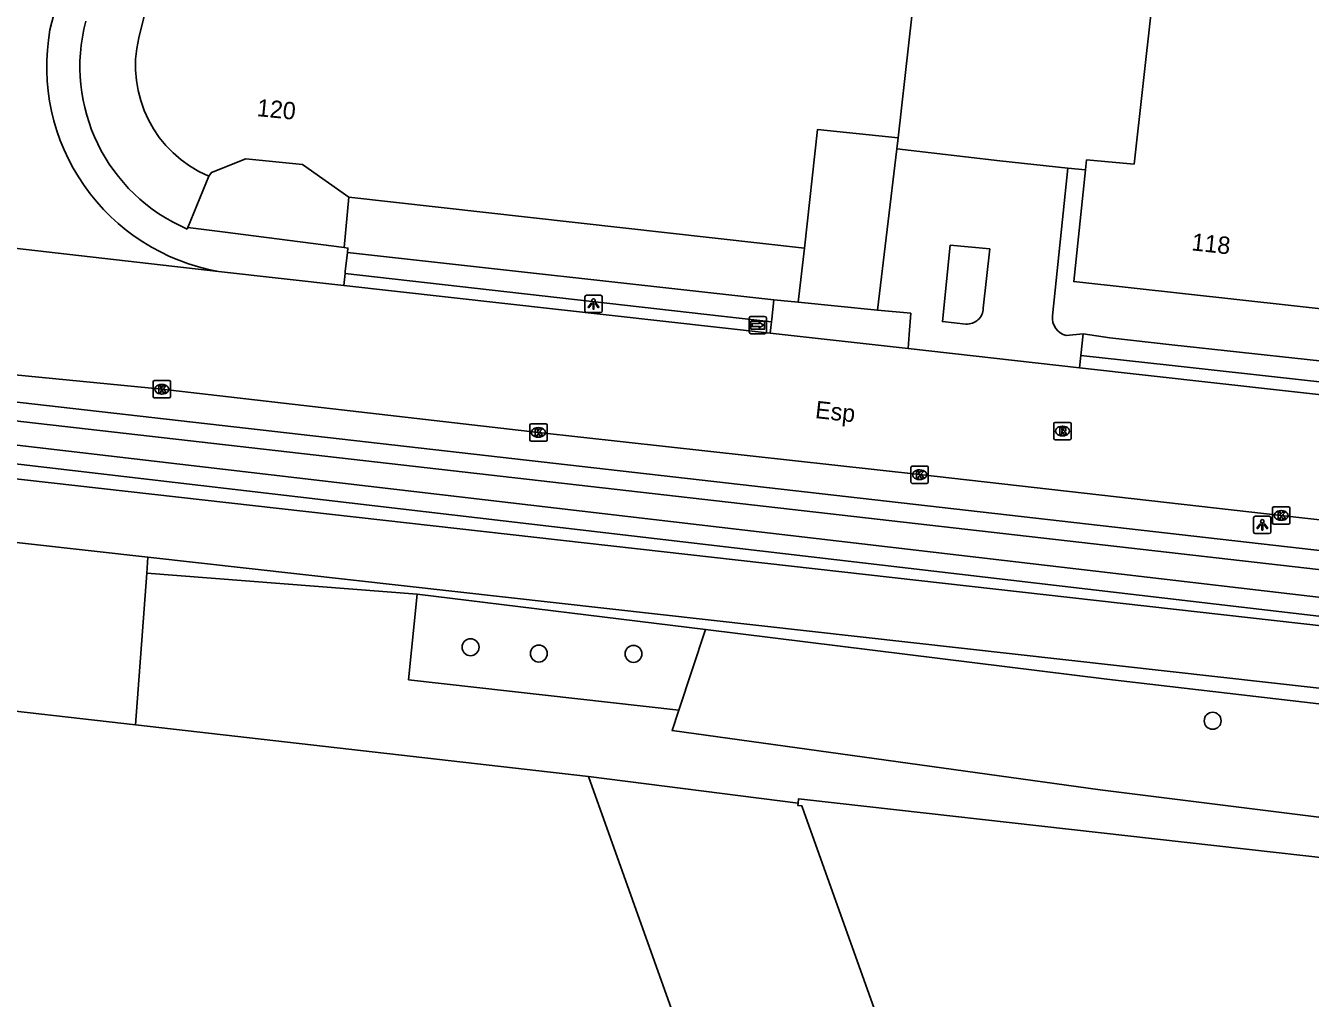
# Model space of a CAD drawing. Extents: x 161389 to 162585, y 388479 to 389761.
# Drawn here: x 162205 to 162279.1, y 388650.1 to 388706.2 of the extents above; entities that cross this region are included whole.
import ezdxf

# ---------------------------------------------------------------- set-up
doc = ezdxf.new("R2010")
doc.units = 0
for name, color, linetype in [('IMGEO_Berm_groen', 7, 'Continuous'), ('IMGEO_Boom', 7, 'Continuous'), ('IMGEO_Erf', 7, 'Continuous'), ('IMGEO_Fietspad_gesloten', 7, 'Continuous'), ('IMGEO_Groenvoorziening', 7, 'Continuous'), ('IMGEO_Hek', 7, 'Continuous'), ('IMGEO_Kolk', 7, 'Continuous'), ('IMGEO_Lichtpunt', 7, 'Continuous'), ('IMGEO_Openbare_ruimte_label', 7, 'Continuous'), ('IMGEO_Pand', 7, 'Continuous'), ('IMGEO_Pand_nummerreeks', 7, 'Continuous'), ('IMGEO_Rijbaan_lokaal_gesloten', 7, 'Continuous'), ('IMGEO_Rijbaan_lokaal_open', 7, 'Continuous'), ('IMGEO_Rioolput', 7, 'Continuous'), ('IMGEO_Voetpad_open', 7, 'Continuous'), ('IMGEO_Waterloop', 7, 'Continuous'), ('IMGEO_Wegwijzer', 7, 'Continuous')]:
    doc.layers.add(name, color=color, linetype=linetype)

msp = doc.modelspace()

# ---------------------------------------------------------------- linework, layer by layer
at = {"layer": 'IMGEO_Berm_groen'}
for points in [[(162195.511, 388685.399), (162199.258, 388685.044), (162309.372, 388672.493), (162313.677, 388672.019)], [(162314.929, 388670.455), (162314.838, 388669.228), (162314.739, 388669.003), (162314.316, 388668.451), (162313.561, 388668.026), (162313.044, 388667.945), (162308.893, 388668.677), (162198.797, 388681.534), (162194.824, 388681.685), (162194.516, 388681.817), (162194.124, 388682.146), (162193.837, 388682.714), (162193.797, 388682.968), (162193.974, 388684.393)], [(162212.05, 388675.493), (162211.982, 388674.58)], [(162227.587, 388673.375), (162211.982, 388674.58)], [(162227.587, 388673.375), (162244.211, 388671.327)], [(162244.211, 388671.327), (162267.366, 388668.474), (162328.021, 388661.404)]]:
    msp.add_lwpolyline(points, dxfattribs=at)
at = {"layer": 'IMGEO_Boom'}
for centre in [(162230.659, 388670.305), (162234.598, 388669.941), (162240.061, 388669.921), (162273.473, 388666.067)]:
    msp.add_circle(centre, 0.489, dxfattribs=at)
at = {"layer": 'IMGEO_Erf'}
msp.add_lwpolyline([(162265.115, 388697.944), (162266.146, 388697.835)], dxfattribs=at)
at = {"layer": 'IMGEO_Fietspad_gesloten'}
for points in [[(162190.209, 388681.612), (162327.081, 388666.21)], [(162212.05, 388675.493), (162188.441, 388678.131)], [(162328.163, 388662.672), (162327.44, 388662.75), (162327.383, 388662.532), (162314.863, 388664.007), (162212.05, 388675.493)]]:
    msp.add_lwpolyline(points, dxfattribs=at)
at = {"layer": 'IMGEO_Groenvoorziening'}
for points in [[(162211.982, 388674.58), (162211.331, 388665.832)], [(162242.681, 388666.67), (162227.085, 388668.43), (162227.587, 388673.375)], [(162242.681, 388666.67), (162244.211, 388671.327)], [(162327.291, 388654.887), (162309.928, 388656.723), (162266.988, 388662.085), (162242.291, 388665.501), (162242.681, 388666.67)], [(162237.455, 388662.849), (162249.555, 388661.32)]]:
    msp.add_lwpolyline(points, dxfattribs=at)
at = {"layer": 'IMGEO_Hek'}
for points in [[(162261.196, 388698.356), (162255.245, 388699.047)], [(162265.115, 388697.944), (162261.196, 388698.356)], [(162266.146, 388697.835), (162265.115, 388697.944)]]:
    msp.add_lwpolyline(points, dxfattribs=at)
at = {"layer": 'IMGEO_Kolk'}
for p, q in [((162212.35, 388684.76), (162212.35, 388685.612)), ((162212.425, 388685.686), (162213.277, 388685.686)), ((162212.838, 388685.466), (162212.863, 388685.466)), ((162213.351, 388685.612), (162213.351, 388684.76)), ((162213.277, 388684.686), (162212.425, 388684.686)), ((162212.861, 388684.906), (162212.836, 388684.906)), ((162234.072, 388682.27), (162234.072, 388683.122)), ((162234.147, 388683.196), (162234.999, 388683.196)), ((162234.56, 388682.976), (162234.585, 388682.976)), ((162235.073, 388683.122), (162235.073, 388682.27)), ((162234.999, 388682.196), (162234.147, 388682.196)), ((162234.583, 388682.416), (162234.558, 388682.416)), ((162256.068, 388679.833), (162256.068, 388680.685)), ((162256.143, 388680.759), (162256.995, 388680.759)), ((162256.556, 388680.539), (162256.581, 388680.539)), ((162257.069, 388680.685), (162257.069, 388679.833)), ((162256.995, 388679.759), (162256.143, 388679.759)), ((162256.579, 388679.979), (162256.554, 388679.979)), ((162276.927, 388677.48), (162276.927, 388678.332)), ((162277.002, 388678.406), (162277.854, 388678.406)), ((162277.415, 388678.186), (162277.44, 388678.186)), ((162277.928, 388678.332), (162277.928, 388677.48)), ((162277.854, 388677.406), (162277.002, 388677.406)), ((162277.438, 388677.626), (162277.413, 388677.626))]:
    msp.add_line(p, q, dxfattribs=at)
for points in [[(162212.35, 388684.76), (162212.35, 388685.612)], [(162212.425, 388685.686), (162213.277, 388685.686)], [(162213.351, 388685.612), (162213.351, 388684.76)], [(162213.277, 388684.686), (162212.425, 388684.686)], [(162212.671, 388685.386), (162212.794, 388685.386), (162212.794, 388685.235), (162212.924, 388685.386), (162213.088, 388685.386), (162212.942, 388685.235), (162213.095, 388684.986), (162212.943, 388684.986), (162212.858, 388685.15), (162212.794, 388685.083), (162212.794, 388684.986), (162212.671, 388684.986), (162212.671, 388685.386)], [(162234.072, 388682.27), (162234.072, 388683.122)], [(162234.147, 388683.196), (162234.999, 388683.196)], [(162234.393, 388682.896), (162234.516, 388682.896), (162234.516, 388682.745), (162234.646, 388682.896), (162234.81, 388682.896), (162234.664, 388682.745), (162234.817, 388682.496), (162234.665, 388682.496), (162234.58, 388682.66), (162234.516, 388682.593), (162234.516, 388682.496), (162234.393, 388682.496), (162234.393, 388682.896)], [(162235.073, 388683.122), (162235.073, 388682.27)], [(162234.999, 388682.196), (162234.147, 388682.196)], [(162256.068, 388679.833), (162256.068, 388680.685)], [(162256.143, 388680.759), (162256.995, 388680.759)], [(162256.389, 388680.459), (162256.512, 388680.459), (162256.512, 388680.308), (162256.642, 388680.459), (162256.806, 388680.459), (162256.66, 388680.308), (162256.813, 388680.059), (162256.661, 388680.059), (162256.576, 388680.223), (162256.512, 388680.156), (162256.512, 388680.059), (162256.389, 388680.059), (162256.389, 388680.459)], [(162257.069, 388680.685), (162257.069, 388679.833)], [(162256.995, 388679.759), (162256.143, 388679.759)], [(162276.927, 388677.48), (162276.927, 388678.332)], [(162277.002, 388678.406), (162277.854, 388678.406)], [(162277.248, 388678.106), (162277.371, 388678.106), (162277.371, 388677.955), (162277.501, 388678.106), (162277.665, 388678.106), (162277.519, 388677.955), (162277.672, 388677.706), (162277.52, 388677.706), (162277.435, 388677.87), (162277.371, 388677.803), (162277.371, 388677.706), (162277.248, 388677.706), (162277.248, 388678.106)], [(162277.928, 388678.332), (162277.928, 388677.48)], [(162277.854, 388677.406), (162277.002, 388677.406)]]:
    msp.add_lwpolyline(points, dxfattribs=at)
for centre, start, end in [((162212.427, 388685.61), 91.55205, 178.44795), ((162212.427, 388685.61), 91.55205, 178.44795), ((162213.275, 388685.61), 1.55205, 88.44795), ((162213.275, 388685.61), 1.55205, 88.44795), ((162212.427, 388684.762), 181.55205, 268.44795), ((162212.427, 388684.762), 181.55205, 268.44795), ((162213.275, 388684.762), 271.55205, 358.44795), ((162213.275, 388684.762), 271.55205, 358.44795), ((162234.149, 388683.12), 91.55205, 178.44795), ((162234.149, 388683.12), 91.55205, 178.44795), ((162234.997, 388683.12), 1.55205, 88.44795), ((162234.997, 388683.12), 1.55205, 88.44795), ((162234.149, 388682.272), 181.55205, 268.44795), ((162234.149, 388682.272), 181.55205, 268.44795), ((162234.997, 388682.272), 271.55205, 358.44795), ((162234.997, 388682.272), 271.55205, 358.44795), ((162256.145, 388680.683), 91.55205, 178.44795), ((162256.145, 388680.683), 91.55205, 178.44795), ((162256.993, 388680.683), 1.55205, 88.44795), ((162256.993, 388680.683), 1.55205, 88.44795), ((162256.145, 388679.835), 181.55205, 268.44795), ((162256.145, 388679.835), 181.55205, 268.44795), ((162256.993, 388679.835), 271.55205, 358.44795), ((162256.993, 388679.835), 271.55205, 358.44795), ((162277.004, 388678.33), 91.55205, 178.44795), ((162277.004, 388678.33), 91.55205, 178.44795), ((162277.852, 388678.33), 1.55205, 88.44795), ((162277.852, 388678.33), 1.55205, 88.44795), ((162277.004, 388677.482), 181.55205, 268.44795), ((162277.004, 388677.482), 181.55205, 268.44795), ((162277.852, 388677.482), 271.55205, 358.44795), ((162277.852, 388677.482), 271.55205, 358.44795)]:
    msp.add_arc(centre, 0.0765, start, end, dxfattribs=at)
for centre, major_axis, ratio, start_param, end_param in [((162212.837, 388685.186), (-0.387, 0.002), 0.722429, 4.712389, 7.853982), ((162212.862, 388685.186), (-0.39, 0.002), 0.717154, 1.570796, 4.712389), ((162234.559, 388682.696), (-0.387, 0.002), 0.722429, 4.712389, 7.853982), ((162234.584, 388682.696), (-0.39, 0.002), 0.717154, 1.570796, 4.712389), ((162256.555, 388680.259), (-0.387, 0.002), 0.722429, 4.712389, 7.853982), ((162256.58, 388680.259), (-0.39, 0.002), 0.717154, 1.570796, 4.712389), ((162277.414, 388677.906), (-0.387, 0.002), 0.722429, 4.712389, 7.853982), ((162277.439, 388677.906), (-0.39, 0.002), 0.717154, 1.570796, 4.712389)]:
    msp.add_ellipse(centre, major_axis=major_axis, ratio=ratio, start_param=start_param, end_param=end_param, dxfattribs=at)
at = {"layer": 'IMGEO_Lichtpunt'}
for p, q in [((162237.256, 388690.513), (162237.256, 388689.706)), ((162237.256, 388690.513), (162237.256, 388689.706)), ((162238.158, 388690.608), (162237.35, 388690.608)), ((162238.158, 388690.608), (162237.35, 388690.608)), ((162238.252, 388689.706), (162238.252, 388690.513)), ((162238.252, 388689.706), (162238.252, 388690.513)), ((162237.35, 388689.612), (162238.158, 388689.612)), ((162237.35, 388689.612), (162238.158, 388689.612)), ((162275.838, 388677.768), (162275.838, 388676.961)), ((162275.838, 388677.768), (162275.838, 388676.961)), ((162276.74, 388677.863), (162275.932, 388677.863)), ((162276.74, 388677.863), (162275.932, 388677.863)), ((162276.834, 388676.961), (162276.834, 388677.768)), ((162276.834, 388676.961), (162276.834, 388677.768)), ((162275.932, 388676.867), (162276.74, 388676.867)), ((162275.932, 388676.867), (162276.74, 388676.867))]:
    msp.add_line(p, q, dxfattribs=at)
for points in [[(162237.63, 388690.177), (162237.669, 388690.149), (162237.481, 388689.887), (162237.443, 388689.914), (162237.63, 388690.177)], [(162237.732, 388690.129), (162237.779, 388690.129), (162237.779, 388689.807), (162237.732, 388689.807), (162237.732, 388690.129)], [(162237.842, 388690.149), (162237.88, 388690.176), (162238.067, 388689.914), (162238.028, 388689.886), (162237.842, 388690.149)], [(162276.212, 388677.432), (162276.251, 388677.404), (162276.063, 388677.142), (162276.025, 388677.169), (162276.212, 388677.432)], [(162276.314, 388677.384), (162276.361, 388677.384), (162276.361, 388677.062), (162276.314, 388677.062), (162276.314, 388677.384)], [(162276.424, 388677.404), (162276.462, 388677.431), (162276.649, 388677.169), (162276.61, 388677.141), (162276.424, 388677.404)]]:
    msp.add_lwpolyline(points, dxfattribs=at)
for centre in [(162237.755, 388690.311), (162276.337, 388677.566)]:
    msp.add_circle(centre, 0.0994, dxfattribs=at)
for centre, start, end in [((162237.35, 388690.513), 90, 180), ((162237.35, 388690.513), 90, 180), ((162238.158, 388690.513), 0, 90), ((162238.158, 388690.513), 0, 90), ((162237.35, 388689.706), 180, 270), ((162237.35, 388689.706), 180, 270), ((162238.158, 388689.706), 270, 0), ((162238.158, 388689.706), 270, 360), ((162275.932, 388677.768), 90, 180), ((162275.932, 388677.768), 90, 180), ((162276.74, 388677.768), 0, 90), ((162276.74, 388677.768), 0, 90), ((162275.932, 388676.961), 180, 270), ((162275.932, 388676.961), 180, 270), ((162276.74, 388676.961), 270, 0), ((162276.74, 388676.961), 270, 360)]:
    msp.add_arc(centre, 0.0946, start, end, dxfattribs=at)
at = {"layer": 'IMGEO_Pand'}
for points in [[(162211.515, 388705.449), (162220.313, 388740.719), (162227.254, 388738.96)], [(162227.254, 388738.96), (162227.068, 388738.207), (162226.351, 388735.221), (162227.54, 388735.088), (162232.571, 388734.536), (162232.77, 388734.513), (162237.406, 388733.976), (162237.604, 388733.953), (162249.955, 388732.564), (162254.514, 388732.048), (162258.439, 388731.604), (162258.899, 388731.55), (162255.335, 388699.679)], [(162266.146, 388697.835), (162266.198, 388698.415), (162268.938, 388698.17), (162272.942, 388734.017), (162287.984, 388732.337), (162288.104, 388732.324), (162284.142, 388696.552)], [(162249.919, 388693.319), (162250.682, 388700.177), (162255.335, 388699.679)], [(162215.552, 388697.486), (162215.711, 388697.693), (162217.697, 388698.472), (162220.967, 388698.149), (162223.633, 388696.259)], [(162266.146, 388697.835), (162265.455, 388691.401), (162281.314, 388689.643), (162282.073, 388696.501), (162284.111, 388696.275)], [(162223.633, 388696.259), (162249.919, 388693.319)], [(162201.171, 388666.993), (162202.802, 388662.297), (162182.158, 388654.923), (162182.252, 388654.637), (162182.743, 388654.798), (162185.543, 388646.914), (162180.831, 388645.223), (162180.558, 388645.977), (162180.164, 388645.887), (162182.655, 388638.891), (162184.222, 388634.491), (162188.677, 388621.975), (162192.555, 388611.083), (162248.797, 388631.105), (162237.455, 388662.849)], [(162211.331, 388665.832), (162201.171, 388666.993)], [(162211.331, 388665.832), (162237.455, 388662.849)], [(162249.555, 388661.32), (162249.539, 388661.179), (162249.773, 388661.153), (162249.791, 388661.103), (162278.169, 388581.632), (162278.061, 388581.594), (162278.245, 388581.061)], [(162323.903, 388652.051), (162324.031, 388653.194), (162250.099, 388661.511), (162249.582, 388661.569), (162249.555, 388661.32)]]:
    msp.add_lwpolyline(points, dxfattribs=at)
msp.add_arc((162218.235, 388703.851), 6.908, 166.62507, 247.14219, dxfattribs=at)
at = {"layer": 'IMGEO_Rijbaan_lokaal_gesloten'}
for points in [[(162206.396, 388705.918), (162206.618, 388706.811)], [(162216.117, 388691.984), (162185.651, 388695.455)], [(162223.34, 388691.176), (162216.117, 388691.984)], [(162247.951, 388688.424), (162223.34, 388691.176)], [(162255.908, 388687.535), (162247.951, 388688.424)], [(162190.731, 388687.591), (162191.691, 388687.487), (162192.948, 388687.248), (162200.409, 388686.41), (162212.852, 388685.186), (162234.573, 388682.697), (162256.569, 388680.26), (162277.429, 388677.907), (162297.925, 388675.602), (162319.739, 388673.126), (162319.871, 388673.113), (162320.835, 388672.971)], [(162265.796, 388686.429), (162255.908, 388687.535)], [(162285.607, 388684.214), (162265.796, 388686.429)]]:
    msp.add_lwpolyline(points, dxfattribs=at)
msp.add_arc((162218.198, 388703.794), 11.992, 169.79791, 260.00489, dxfattribs=at)
at = {"layer": 'IMGEO_Rijbaan_lokaal_open'}
for points in [[(162255.335, 388699.679), (162255.245, 388699.047)], [(162255.245, 388699.047), (162254.13, 388689.743)], [(162255.245, 388699.047), (162261.196, 388698.356), (162265.115, 388697.944)], [(162265.115, 388697.944), (162264.238, 388689.414)], [(162249.919, 388693.319), (162249.57, 388690.204)], [(162260.627, 388693.292), (162258.332, 388693.496), (162257.881, 388689.092), (162259.237, 388688.948)], [(162260.241, 388689.861), (162260.627, 388693.292)], [(162254.13, 388689.743), (162249.57, 388690.204)], [(162254.13, 388689.743), (162256.055, 388689.574), (162255.966, 388688.342), (162255.908, 388687.535)], [(162265.031, 388688.292), (162265.999, 388688.392)], [(162265.86, 388687.132), (162265.999, 388688.392)], [(162265.86, 388687.132), (162265.796, 388686.429)]]:
    msp.add_lwpolyline(points, dxfattribs=at)
for centre, radius, start, end in [((162259.305, 388689.881), 0.936, 265.81307, 358.75135), ((162265.253, 388689.29), 1.023, 173.04804, 257.45528)]:
    msp.add_arc(centre, radius, start, end, dxfattribs=at)
at = {"layer": 'IMGEO_Rioolput'}
for p, q in [((162264.311, 388682.35), (162264.311, 388683.202)), ((162264.386, 388683.276), (162265.238, 388683.276)), ((162265.312, 388683.202), (162265.312, 388682.35)), ((162264.822, 388682.496), (162264.797, 388682.496)), ((162264.799, 388683.056), (162264.824, 388683.056)), ((162265.238, 388682.276), (162264.386, 388682.276))]:
    msp.add_line(p, q, dxfattribs=at)
for points in [[(162264.311, 388682.35), (162264.311, 388683.202)], [(162264.386, 388683.276), (162265.238, 388683.276)], [(162265.312, 388683.202), (162265.312, 388682.35)], [(162264.9, 388682.974), (162264.648, 388682.976), (162264.648, 388682.576)], [(162264.648, 388682.576), (162264.772, 388682.576), (162264.772, 388682.738), (162264.783, 388682.738)], [(162264.826, 388682.895), (162264.772, 388682.895), (162264.772, 388682.814)], [(162264.772, 388682.814), (162264.824, 388682.814)], [(162264.83, 388682.709), (162264.901, 388682.576), (162265.041, 388682.576), (162264.976, 388682.702)], [(162265.238, 388682.276), (162264.386, 388682.276)]]:
    msp.add_lwpolyline(points, dxfattribs=at)
for centre, radius, start, end in [((162264.388, 388683.2), 0.0765, 91.55205, 178.44795), ((162264.388, 388683.2), 0.0765, 91.55205, 178.44795), ((162265.236, 388683.2), 0.0765, 1.55205, 88.44795), ((162265.236, 388683.2), 0.0765, 1.55205, 88.44795), ((162264.782, 388682.685), 0.0533, 26.02933, 88.69889), ((162264.808, 388683.003), 0.19, 274.7715, 282.96867), ((162264.832, 388682.799), 0.0964, 77.00612, 93.18647), ((162264.846, 388682.856), 0.0378, 276.66336, 79.67722), ((162264.899, 388682.864), 0.109, 350.36119, 89.41601), ((162264.897, 388682.864), 0.112, 277.58423, 350.98172), ((162264.881, 388682.649), 0.108, 29.51342, 73.79051), ((162264.388, 388682.352), 0.0765, 181.55205, 268.44795), ((162264.388, 388682.352), 0.0765, 181.55205, 268.44795), ((162265.236, 388682.352), 0.0765, 271.55205, 358.44795), ((162265.236, 388682.352), 0.0765, 271.55205, 358.44795)]:
    msp.add_arc(centre, radius, start, end, dxfattribs=at)
for centre, major_axis, ratio, start_param, end_param in [((162264.798, 388682.776), (-0.387, 0.002), 0.722429, 4.712389, 7.853982), ((162264.823, 388682.776), (-0.39, 0.002), 0.717154, 1.570796, 4.712389)]:
    msp.add_ellipse(centre, major_axis=major_axis, ratio=ratio, start_param=start_param, end_param=end_param, dxfattribs=at)
at = {"layer": 'IMGEO_Voetpad_open'}
for points in [[(162214.345, 388694.525), (162215.552, 388697.486)], [(162223.374, 388693.364), (162223.633, 388696.259)], [(162214.313, 388694.428), (162214.345, 388694.525)], [(162214.345, 388694.525), (162216.358, 388694.266), (162223.374, 388693.364)], [(162223.557, 388693.066), (162223.587, 388693.331), (162223.374, 388693.364)], [(162223.557, 388693.066), (162223.432, 388691.98), (162223.419, 388691.863)], [(162248.149, 388690.348), (162223.557, 388693.066)], [(162223.419, 388691.863), (162223.34, 388691.176)], [(162248.018, 388689.075), (162223.419, 388691.863)], [(162248.018, 388689.075), (162248.034, 388689.229), (162248.149, 388690.348)], [(162249.57, 388690.204), (162248.149, 388690.348)], [(162247.951, 388688.424), (162248.018, 388689.075)], [(162265.999, 388688.392), (162267.535, 388688.159), (162271.112, 388687.748), (162282.834, 388686.471)], [(162285.711, 388684.934), (162270.971, 388686.569), (162265.86, 388687.132)]]:
    msp.add_lwpolyline(points, dxfattribs=at)
msp.add_arc((162218.309, 388703.798), 10.186, 165.09544, 246.90522, dxfattribs=at)
at = {"layer": 'IMGEO_Waterloop'}
for points in [[(162312.727, 388671.029), (162309.251, 388671.412), (162199.145, 388683.962), (162195.97, 388684.262)], [(162195.347, 388683.225), (162195.481, 388683.01), (162195.633, 388682.868), (162195.82, 388682.736), (162198.881, 388682.62), (162309.051, 388669.754), (162312.207, 388669.198)]]:
    msp.add_lwpolyline(points, dxfattribs=at)
at = {"layer": 'IMGEO_Wegwijzer'}
for p, q in [((162246.737, 388688.49), (162246.737, 388689.29)), ((162246.737, 388689.29), (162246.737, 388688.49)), ((162246.837, 388689.39), (162247.627, 388689.39)), ((162247.627, 388689.39), (162246.837, 388689.39)), ((162247.727, 388689.29), (162247.727, 388688.49)), ((162247.727, 388688.49), (162247.727, 388689.29)), ((162247.627, 388688.39), (162246.837, 388688.39)), ((162246.837, 388688.39), (162247.627, 388688.39))]:
    msp.add_line(p, q, dxfattribs=at)
for points in [[(162246.838, 388689.122), (162247.626, 388689.122), (162247.626, 388688.658), (162246.838, 388688.658), (162246.838, 388689.122)], [(162246.903, 388688.974), (162246.903, 388688.89), (162246.903, 388688.806), (162247.314, 388688.806), (162247.314, 388688.723), (162247.561, 388688.89), (162247.314, 388689.057), (162247.314, 388688.974), (162246.903, 388688.974)]]:
    msp.add_lwpolyline(points, dxfattribs=at)
for centre, start, end in [((162246.837, 388689.29), 90, 180), ((162246.837, 388689.29), 90, 180), ((162247.627, 388689.29), 0, 90), ((162247.627, 388689.29), 360, 90), ((162246.837, 388688.49), 180, 270), ((162246.837, 388688.49), 180, 270), ((162247.627, 388688.49), 270, 0), ((162247.627, 388688.49), 270, 0)]:
    msp.add_arc(centre, 0.1, start, end, dxfattribs=at)

# ---------------------------------------------------------------- texts
at = {"layer": 'IMGEO_Openbare_ruimte_label'}
msp.add_text('Esp', height=1, rotation=353.62818, dxfattribs=at).set_placement((162250.507, 388683.53))
at = {"layer": 'IMGEO_Pand_nummerreeks'}
for s, rotation, p in [('120', 354.35881, (162218.302, 388700.944)), ('118', 353.72474, (162272.222, 388693.204))]:
    msp.add_text(s, height=1, rotation=rotation, dxfattribs=at).set_placement(p)

doc.saveas('drawing.dxf')
